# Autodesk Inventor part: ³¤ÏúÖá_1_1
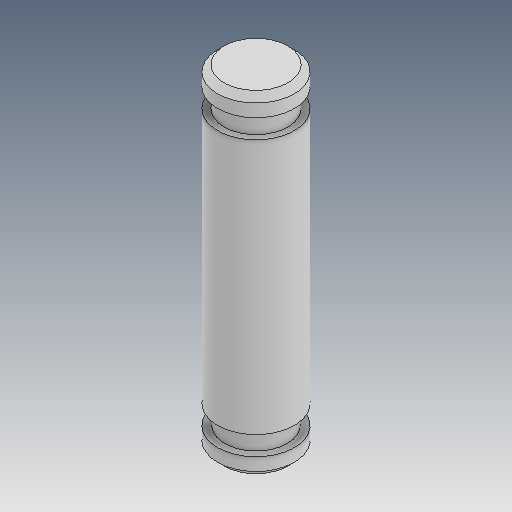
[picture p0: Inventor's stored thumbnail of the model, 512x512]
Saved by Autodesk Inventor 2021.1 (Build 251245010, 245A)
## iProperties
Created: 2019-04
Part Number: ³¤ÏúÖá_1_1
Material: Ogólny
Document SubType Name: Modeling
Designer: user
Density: 1 g/cm^3
Appearance: Domyślna
Author: user
Revision Number: ÈÎºÎ
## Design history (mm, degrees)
feature "ÊäÈë1"
node "Bryła1"
